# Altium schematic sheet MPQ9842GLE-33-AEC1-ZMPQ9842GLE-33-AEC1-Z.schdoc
size 127 x 101 mm
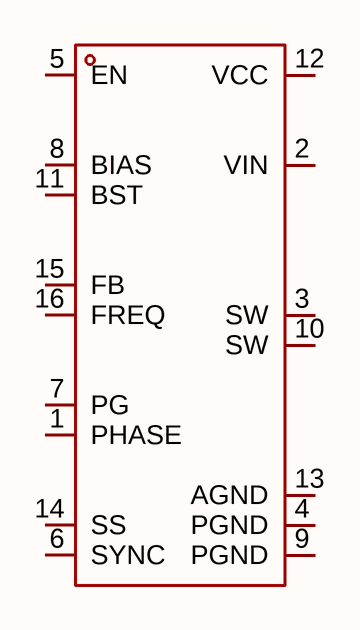
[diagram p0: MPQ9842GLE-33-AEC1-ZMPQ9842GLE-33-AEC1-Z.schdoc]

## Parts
U?  mpq9842gle-33-aec1-z  [QFN-16_L4.0-W3.0-P0.60-BL_MPQ4430GL-Z]  (value not drawn)

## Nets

Not connected (* = marked no-connect by the designer): U? 1(PHASE) 2(VIN) 3(SW) 4(PGND) 5(EN) 6(SYNC) 7(PG) 8(BIAS) 9(PGND) 10(SW) 11(BST) 12(VCC) 13(AGND) 14(SS) 15(FB) 16(FREQ)

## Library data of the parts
U? = mpq9842gle-33-aec1-z: 功能类型:降压型;工作电压:3.3V~36V;输出电压:3.3V;输出电流:2A;输出类型:固定;; Manufacturer: MPS(芯源); AddInBom: yes; ModelId: 6786fb52d99947488eed27d13d5f8cbe; ModelName: QFN-16_L4.0-W3.0-H1.0-P0.60; ModelTransform: 158.267,118.8974,0,180,0,0,0,0,0; Function: 降压型; Output Voltage: 3.3V; Output Current: 2A; Frequency - Switching: 2.5MHz; Synchronous Rectifier: 是; Number of Outputs: 1; Topology: 降压式; Quiescent Current: 14uA; Switch tube (built-in/external): 内置; Output Type: 固定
